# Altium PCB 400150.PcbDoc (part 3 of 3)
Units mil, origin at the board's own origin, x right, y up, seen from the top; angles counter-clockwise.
Board outline 4000 x 2500 mil, 4 copper layers (Top Layer, Mid-Layer 1, Mid-Layer 2, Bottom Layer), stack 62.293 mil thick; 200 components, 153 nets, 913 pads, 613 vias.
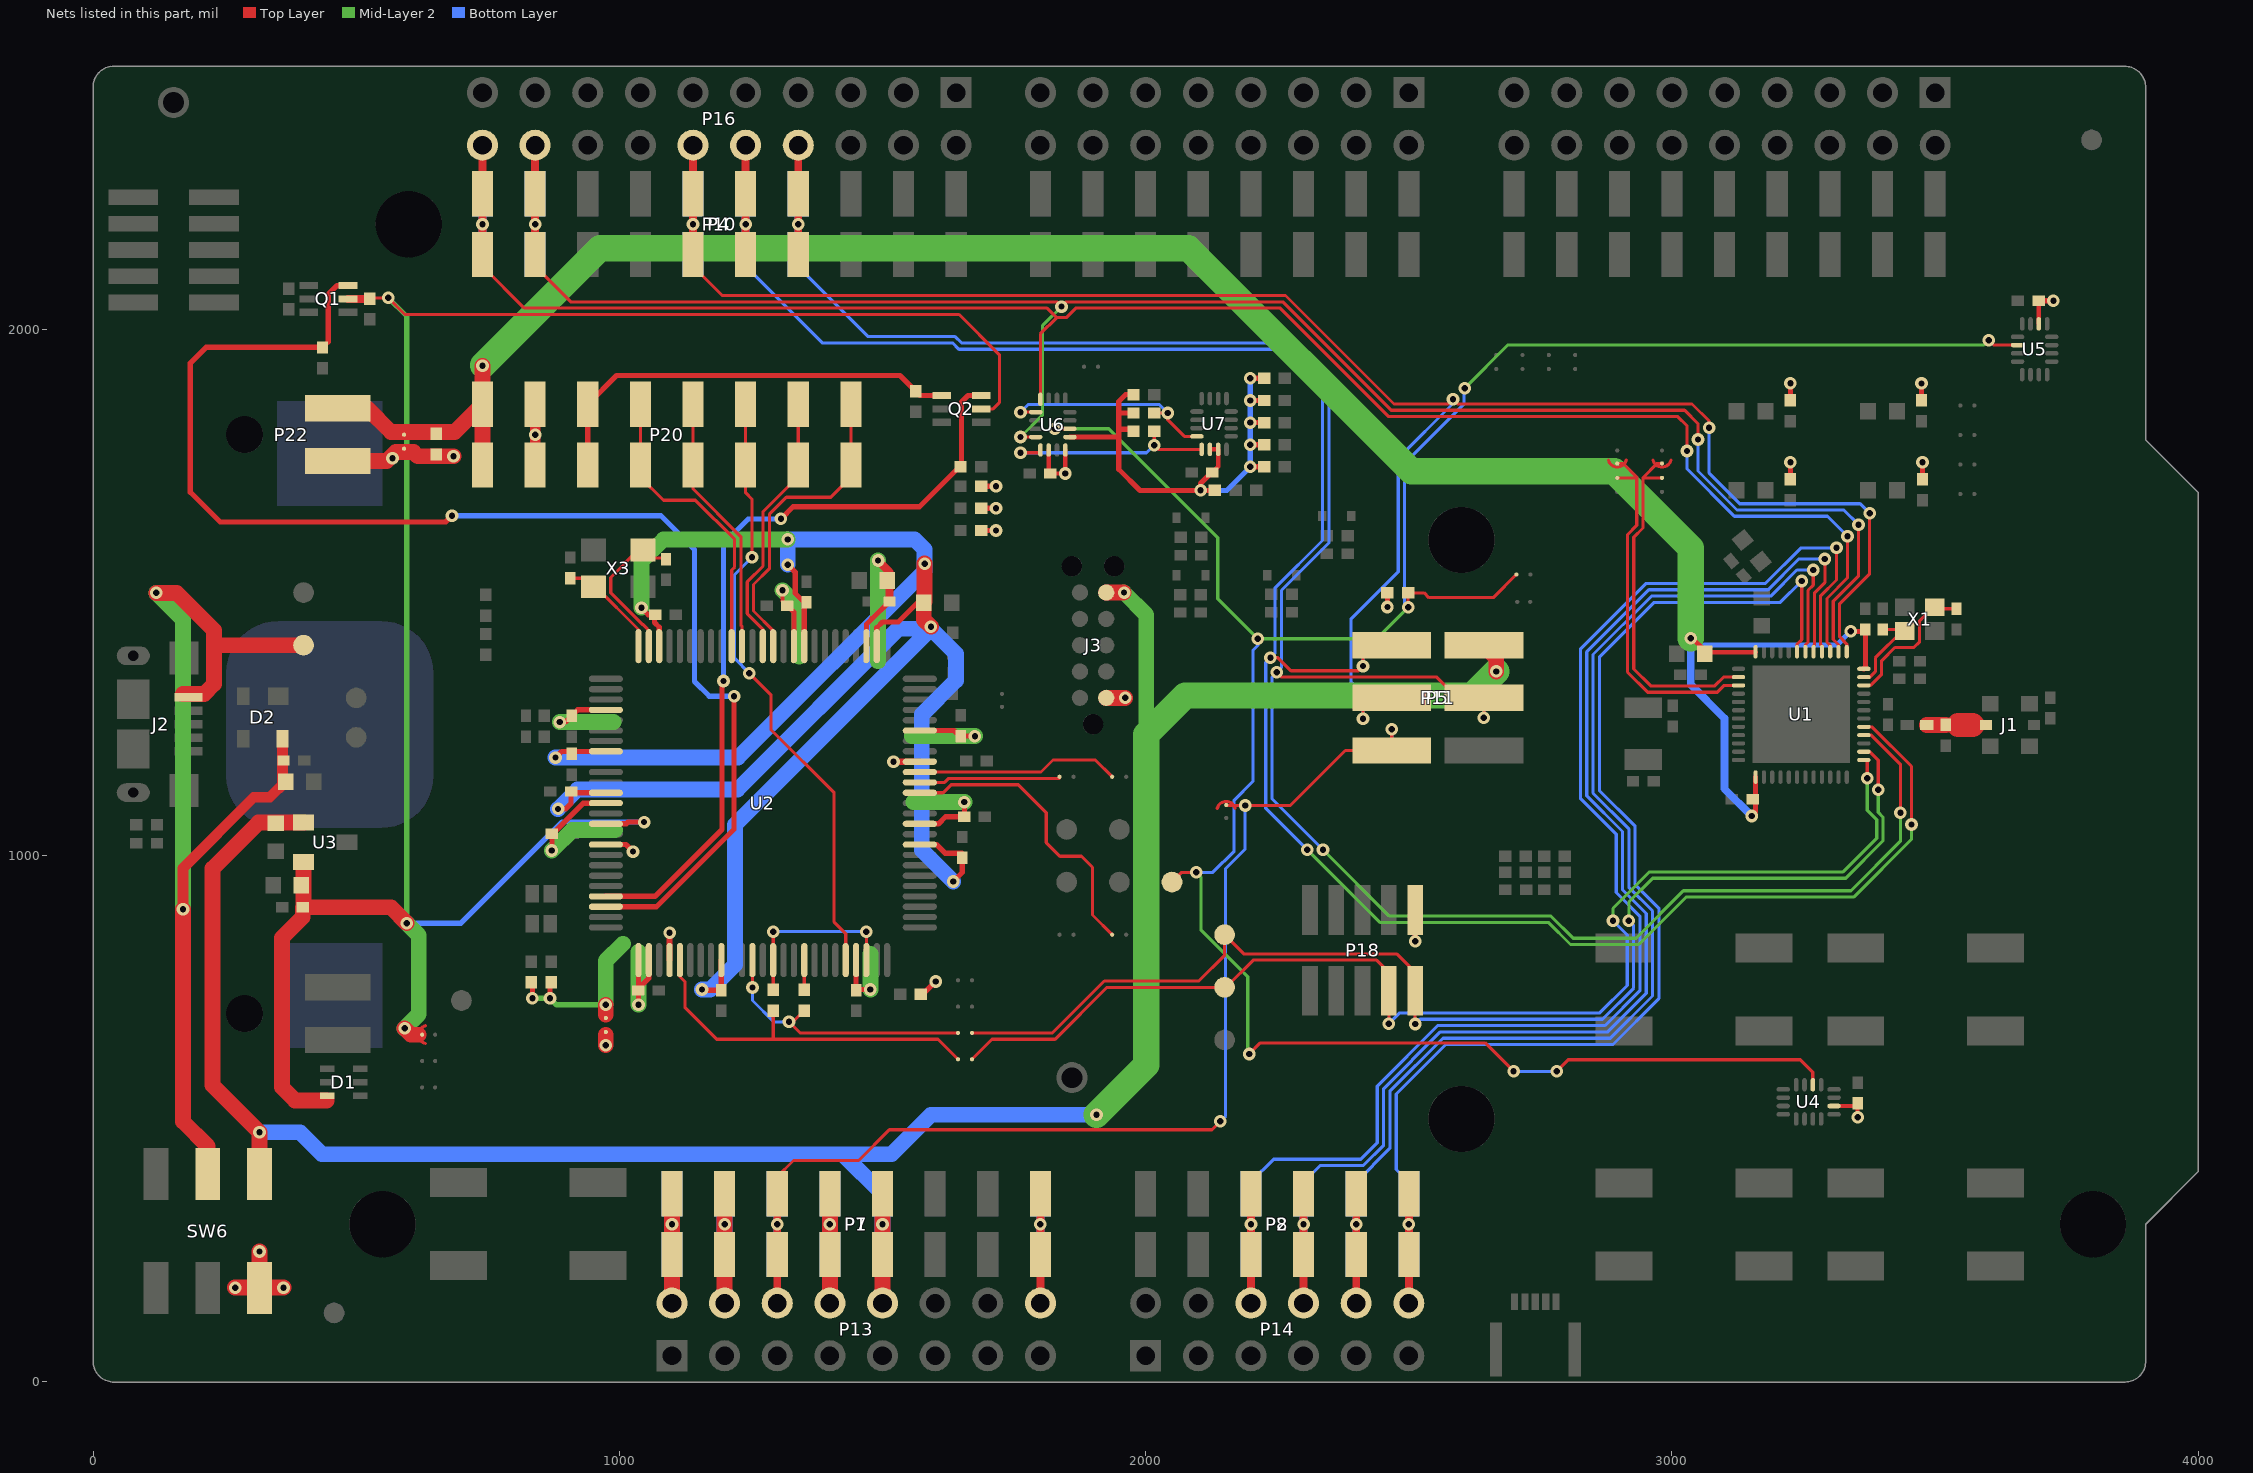
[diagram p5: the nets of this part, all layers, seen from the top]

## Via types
v1: diameter 24, hole 12, Top Layer to Bottom Layer, tented both sides, 576 vias
v2: diameter 24, hole 12, Top Layer to Bottom Layer, 21 vias
v3: diameter 25.98, hole 12.99, Top Layer to Bottom Layer, tented both sides, 16 vias

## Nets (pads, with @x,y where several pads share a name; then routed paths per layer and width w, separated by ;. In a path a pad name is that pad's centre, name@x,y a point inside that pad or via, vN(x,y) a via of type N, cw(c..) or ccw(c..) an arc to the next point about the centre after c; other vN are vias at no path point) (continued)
P0.23: P4.4 P5.4 P10.4 P11.4 P16.8 U1.28 | length 4457.1
  Top Layer w6: v1(2249,1348) 2258,1339 2553,1339 2592.4,1299.6 P5.4@2642.5,1299.6 v1(2642.5,1261.6) ; U1.28@3364.56,1228.79 3378.54,1228.79 3434,1173.33 v1(3434,1081.03)
  Top Layer w15: P4.4@1340,2118.6 v1(1340,2199.6) P4.4@1340,2257.28 P16.8@1340,2349.6
  Mid-Layer 2 w6: v1(2337,1011) 2463,885 2770.03,885 2812.03,843 2931.71,843 3021.71,933 3340.03,933 3434,1026.97 v1(3434,1081.03)
  Bottom Layer w6: P10.4@1340,2141.92 1340,2118.6 1472.6,1986 1638,1986 1650,1974 2287.65,1974 2348,1913.65 2348,1799 ; v1(2337,1011) 2240,1108 2240,1339 v1(2249,1348) 2258,1357 2258,1503.71 2348,1593.71 2348,1811.14 ; v1(2642.5,1261.6) 2642.5,1299.6 P11.4@2666.22,1299.6
  Bottom Layer w15: P10.4@1340,2141.92 v1(1340,2199.6) P10.4@1340,2257.28
P0.24: P4.5 P5.1 P10.5 P11.1 P16.10 U1.29 | length 4378.7
  Top Layer w6: v1(2237,1376) 2250.82,1376 2275.82,1351 2404,1351 v1(2413,1360) P5.1@2413,1399 ; U1.29@3364.56,1244.54 3379.76,1244.54 3455,1169.3 v1(3455,1059.03)
  Top Layer w15: P4.5@1240,2119.6 v1(1240,2199.6) P4.5@1240,2257.28 P16.10@1240,2349.6
  Mid-Layer 2 w6: v1(2307,1011) 2445,873 2765.06,873 2807.06,831 2936.68,831 3026.68,921 3345,921 3455,1031 v1(3455,1059.03)
  Bottom Layer w6: P10.5@1240,2141.92 1240,2119.6 1385.6,1974 1633.03,1974 1645.03,1962 2282.68,1962 2336,1908.68 2336,1799 ; v1@2237,1375 v1(2237,1376) ; v1(2307,1011) 2228,1090 2228,1367 v1(2237,1376) ; 2336,1816.11 2336,1598.68 2246,1508.68 2246,1385 v1(2237,1376) ; v1(2413,1360) P11.1@2413,1400
  Bottom Layer w15: P10.5@1240,2141.92 v1(1240,2199.6) P10.5@1240,2257.28
P0.25: P4.6 P5.3 P10.6 P11.3 P16.12 U1.37 | length 3916.4
  Top Layer w6: P4.6@1140,2119.6 1195.6,2064 2265.71,2064 2471.71,1858 2575,1858 v1(2584,1867) 2593,1858 3038,1858 3070.46,1825.54 v1(3070.46,1812.54) ; v1(2413,1260) P5.3@2413,1298 ; U1.37@3332.08,1387.25 3332.08,1401.77 3318.46,1415.38 3318.46,1478.52 3375.46,1535.52 v1(3375.46,1650.54)
  Top Layer w15: P4.6@1140,2119.6 v1(1140,2199.6) P4.6@1140,2257.28 P16.12@1140,2349.6
  Bottom Layer w6: v1(2413,1260) P11.3@2413,1298 ; P11.3@2420.19,1299.6 P11.3@2443.78,1299.6 2420.4,1299.6 2390,1330 2390,1449 2480,1539 2480,1754.87 2584,1858.87 v1(2584,1867) ; v1(3070.46,1812.54) 3070.46,1726.51 3128.44,1668.54 3357.46,1668.54 v1(3375.46,1650.54)
  Bottom Layer w15: P10.6@1140,2141.92 v1(1140,2199.6) P10.6@1140,2257.28
P0.26: P4.9 P10.9 P16.18 U1.38 U6.12 | length 3697.8
  Top Layer w6: P4.9@840,2119.6 907.6,2052 1831,2052 v1(1840,2043) 1849,2052 2260.68,2052 2466.68,1846 3024,1846 3049.46,1820.54 v1(3049.46,1790.54) ; v1(1762.14,1795.15) U6.12@1791.14,1795.15 ; U1.38@3316.33,1387.25 3316.33,1400.55 3306.46,1410.41 3306.46,1483.49 3354.46,1531.49 v1(3354.46,1628.54)
  Top Layer w15: P4.9@840,2119.6 v1(840,2199.6) P4.9@840,2257.28 P16.18@840,2349.6
  Mid-Layer 2 w6: v1(1762.14,1795.15) 1804.31,1837.31 1804.31,2007.31 v1(1840,2043)
  Bottom Layer w6: v1(3049.46,1790.54) 3049.46,1730.54 3123.46,1656.54 3326.46,1656.54 v1(3354.46,1628.54)
  Bottom Layer w15: P10.9@840,2141.92 v1(840,2199.6) P10.9@840,2257.28
P0.27: P4.10 P10.10 P16.20 U1.39 U6.8 | length 3620
  Top Layer w6: P4.10@740,2119.6 819.6,2040 1812.82,2040 1830.82,2022 ; U6.8@1800,1867 1800,1991.18 1830.82,2022 ; v1(3028.46,1768.54) 3028.46,1816.54 3011,1834 2461.71,1834 2255.71,2040 1867,2040 1849,2022 1830.82,2022 ; U1.39@3300.58,1387.25 3300.58,1399.32 3294.46,1405.44 3294.46,1488.46 3333.46,1527.46 v1(3333.46,1606.54)
  Top Layer w15: P4.10@740,2119.6 v1(740,2199.6) P4.10@740,2257.28 P16.20@740,2349.6
  Bottom Layer w6: v1(3028.46,1768.54) 3028.46,1734.56 3118.49,1644.54 3295.46,1644.54 v1(3333.46,1606.54)
  Bottom Layer w15: P10.10@740,2141.92 v1(740,2199.6) P10.10@740,2257.28
P0.28: P2.3 P8.3 P14.6 U1.40 | length 2770.9
  Top Layer w6: U1.40@3284.83,1387.25 3284.83,1398.1 3282.46,1400.47 3282.46,1493.54 3312.46,1523.54 v1(3312.46,1584.54)
  Top Layer w15: P14.6@2200,149.6 P2.3@2200,241.92 v1(2200,299.6) P2.3@2200,357.28
  Bottom Layer w6: P8.3@2200,357.28 2200,380 2243,423 2408.68,423 2440,454.32 2440,562 2555,677 2872.94,677 2939,743.06 2939,884.82 2894,929.82 2894,1040.76 2826,1108.76 2826,1392 2951,1517 3177.74,1517 3245.27,1584.54 v1(3312.46,1584.54)
  Bottom Layer w15: P8.3@2200,241.92 v1(2200,299.6) P8.3@2200,357.28
P0.29: P2.4 P8.4 P14.8 U1.41 | length 2614.3
  Top Layer w6: U1.41@3269.09,1387.25 3269.09,1398.87 3270.46,1400.25 3270.46,1498.54 3290.46,1518.54 v1(3290.46,1563.54)
  Top Layer w15: P14.8@2300,149.6 P2.4@2300,241.92 v1(2300,299.6) P2.4@2300,357.28
  Bottom Layer w6: P8.4@2300,379.6 2331.4,411 2413.68,411 2452,449.32 2452,557 2560,665 2877.91,665 2951,738.09 2951,889.79 2906,934.79 2906,1045.74 2838,1113.74 2838,1386.94 2956.06,1505 3182.71,1505 3241.24,1563.54 v1(3290.46,1563.54)
  Bottom Layer w15: P8.4@2300,241.92 v1(2300,299.6) P8.4@2300,379.6
P0.30: P2.5 P8.5 P14.10 U1.42 | length 2451.5
  Top Layer w6: U1.42@3253.34,1387.25 3253.34,1400.09 3258.46,1405.22 3258.46,1503.79 3268.46,1513.79 v1@3268.46,1533.54
  Top Layer w15: P14.10@2400,149.6 P2.5@2400,241.92 v1(2400,299.6) P2.5@2400,357.28
  Bottom Layer w6: P8.5@2400,379.6 2464,443.6 2464,552.03 2564.97,653 2882.88,653 2963,733.12 2963,894.76 2918,939.76 2918,1050.71 2850,1118.71 2850,1381.97 2961.03,1493 3187.68,1493 3237.21,1542.54 v1(3268.46,1542.54)
  Bottom Layer w15: P8.5@2400,241.92 v1(2400,299.6) P8.5@2400,379.6
P0.31: P2.6 P8.6 P14.12 U1.43 | length 2374.7
  Top Layer w6: U1.43@3237.59,1387.25 3237.59,1401.32 3246.46,1410.19 v1(3246.46,1521.54)
  Top Layer w15: P14.12@2500,149.6 P2.6@2500,241.92 v1(2500,299.6) P2.6@2500,357.28
  Bottom Layer w6: P8.6@2500,357.28 2500,379.6 2476,403.6 2476,547.06 2569.94,641 2887.85,641 2975,728.15 2975,899.73 2930,944.73 2930,1055.68 2862,1123.68 2862,1377 2966,1481 3205.93,1481 v1(3246.46,1521.54)
  Bottom Layer w15: P8.6@2500,241.92 v1(2500,299.6) P8.6@2500,357.28
PB5: Q2.3 R10.2 U2.97 | length 1490
  Top Layer w10: U2.97@974.38,922.43 1067.83,922.43 1195,1049.6 1195,1328.6 v1(1198,1331.6) ; v1(1307,1639.6) 1330,1662.6 1570.28,1662.6 R10.2@1645.75,1738.07 ; R10.2@1650,1739.77 1650,1861.6 1662.59,1874.19 Q2.3@1687.4,1874.19
  Bottom Layer w10: v1(1198,1331.6) 1198,1592.6 1245,1639.6 v1(1307,1639.6)
PB6: Q1.3 R11.2 U2.98 | length 2568
  Top Layer w10: R11.2@436,1965.29 R11.2@436.31,1965.6 ; Q1.3@484.4,2083.19 463.59,2083.19 447,2066.6 447,1976.29 R11.2@436.31,1965.6 ; v1(682,1645.6) 670,1633.6 241.68,1633.6 185,1690.28 185,1935.6 215,1965.6 R11.2@436.31,1965.6 ; U2.98@974.38,902.75 1070.78,902.75 1218,1049.97 v1(1218,1302.6) ; v1@1221,1302.6 v1@1221,1304.6
  Bottom Layer w10: v1(682,1645.6) 1079,1645.6 1143,1581.6 1143,1330.6 1171,1302.6 v1@1217,1302.6
RESET: P1.3 P5.5 P7.3 P11.5 P13.6 SB17.1 | length 2297.9
  Top Layer w6: P1.3@1300,357.28 1300,389.6 1331,420.6 1454.6,420.6 1513,479 2126,479 v1(2142,495) ; SB17.1@2154,1095 2167.61,1095 v1(2189,1095) 2274.9,1095 2379.5,1199.6 P5.5@2467.5,1199.6 ; P5.5@2467.69,1199.79 v1(2467.69,1240)
  Top Layer w15: P13.6@1300,149.6 P1.3@1300,241.92 v1(1300,299.6) P1.3@1300,357.28
  Bottom Layer w6: v1(2142,495) 2152,505 2152,975.32 2189,1012.32 v1(2189,1095) ; P11.5@2467.69,1199.6 v1(2467.69,1240)
  Bottom Layer w15: P7.3@1300,241.92 v1(1300,299.6) P7.3@1300,357.28
RF: C13.1 J1.1 L1.2 | length 62.9
  Top Layer w20: C13.1@3519.87,1248.16 C13.1@3520,1248.29
  Top Layer w30: L1.2@3484.17,1248.16 C13.1@3519.87,1248.16
  Top Layer w45: 3543.87,1248.16 3570.87,1248.16
RTS: SB24.2 U2.39 | length 576.5
  Top Layer w6: U2.39@1570.83,1119.28 1615.26,1119.28 1630.63,1134.65 1758,1134.65 1811.05,1081.59 1811.05,1024.55 1837,998.6 1878,998.6 1899,977.6 1899,887.01 SB24.2@1936.4,849.6
RXD: SB23.2 U2.40 | length 268.7
  Top Layer w6: U2.40@1570.83,1138.97 1617.98,1138.97 1625.66,1146.65 SB23.2@1836.4,1146.65
SCL_EXT: R30.1 U6.9 U7.12 | length 428.2
  Top Layer w6: v1(1762.14,1842.39) U6.9@1791.14,1842.39 ; R30.1@2016.31,1840.77 v1(2041.94,1840.77) 2041.94,1828 2073.56,1796.38 U7.12@2097.45,1796.38
  Bottom Layer w6: v1(1762.14,1842.39) 1776.52,1856.77 2025.39,1856.77 ; 2025.71,1857 v1(2041.94,1840.77)
SDA_EXT: R29.1 U6.13 U7.13 | length 417.5
  Top Layer w6: v1(1762.14,1765.15) U6.13@1800.14,1765.15 ; R29.1@2016.31,1805.77 v1(2016.31,1779.77) 2024.31,1771.77 U7.13@2106.31,1771.77
  Bottom Layer w6: v1(1762.14,1765.15) 2001.68,1765.15 v1(2016.31,1779.77)
SH_GND_DETECT: P20.8 U2.62 | length 601.1
  Top Layer w6: U2.62@1292.29,1397.83 1292.29,1427.31 1255,1464.6 1255,1514.92 1285,1544.92 1285,1648.2 1317.4,1680.6 1402,1680.6 1440,1718.6 P20.8@1440,1857.28
SH_RESET: P20.7 U2.63 | length 511.9
  Top Layer w6: U2.63@1272.61,1397.83 1272.61,1430.02 1243,1459.63 1243,1519.89 1273,1549.89 1273,1653.2 1340,1720.2 P20.7@1340,1741.92 P20.7@1340,1857.28
SH_SWDCLK: P20.5 U2.65 | length 498.1
  Top Layer w6: P20.5@1140,1857.28 1140,1696.6 1231,1605.6 1231,1437.69 1233.24,1435.45 U2.65@1233.24,1397.83
SH_SWDIO: P20.4 U2.66 | length 567.7
  Top Layer w6: P20.4@1040,1741.92 1040,1718.88 1083.84,1675.04 1144.56,1675.04 1219,1600.6 1219,1548.04 1213.55,1542.59 U2.66@1213.55,1397.83 ; P20.4@1040,1745.6 P20.4@1040,1857.28
SH_SWO: P20.6 U2.21 | length 1162
  Top Layer w6: P20.6@1240,1857.28 P20.6@1240,1741.92 1240,1689.04 1252,1677.04 v1(1252,1566.92) ; v1(1247,1346.6) 1288,1305.6 1288,1239.57 1408,1119.57 1408,873.6 1430.09,851.51 U2.21@1430.09,801.37
  Bottom Layer w6: v1(1247,1346.6) 1219,1374.6 1219,1533.92 v1(1252,1566.92)
SH_VTG: P20.3 Q2.4 R9.1 | length 941.6
  Top Layer w6: P20.3@940,1741.92 P20.3@940,1857.28
  Top Layer w10: P20.3@940,1741.92 P20.3@940,1857.28 994.72,1912 1533.28,1912 R9.1@1563,1882.29 1571.09,1874.19 Q2.4@1612.6,1874.19
SHIELD_DETECT: R39.1 SB19.2 TP15.1 U4.2 U5.2 U6.2 | length 4866.8
  Top Layer w6: v1(1827.52,1810.9) U6.2@1856.1,1810.9 ; TP15.1@2050,949.6 2068.4,968 v1(2096,968) ; v1(2197,623) 2218,644 2644.99,644 v1(2699,590) ; v1(2499,1472) 2498.69,1472.31 R39.1@2498.69,1499 2529,1499 2538,1490 2660.4,1490 SB19.2@2704.4,1534 ; v1(2781,590) 2803,612 3243.66,612 3267.54,588.12 U4.2@3267.54,564.48 ; v1(3602,1979) 3611,1970 3656.39,1970 U5.2@3656.52,1969.87
  Mid-Layer 2 w6: v1(1827.52,1810.9) 1930.1,1810.9 2137,1604 2137,1488 v1(2213,1412) 2439,1412 v1(2499,1472) ; v1(2096,968) 2105,959 2105,859 2194,770 2194,626 v1(2197,623) ; v1(2606,1888) 2688,1970 3593,1970 v1(3602,1979)
  Bottom Layer w6: v1(2096,968) 2127.71,968 2168,1008.29 2168,1105 2204,1141 2204,1390 2213,1399 v1(2213,1412) ; v1(2499,1472) 2492,1479 2492,1745.3 2605,1858.3 2605,1887 v1(2606,1888) ; v1(2699,590) v1(2781,590)
SWDCLK: P18.4 SB21.1 TP10.1 U1.25 | length 2327.9
  Top Layer w6: SB21.1@1670.02,613 1708.02,651 1827.97,651 1926.57,749.6 TP10.1@2150,749.6 2152.6,749.6 2204.23,801.23 2438.77,801.23 2462,778 P18.4@2462,746.23 ; v1(2462,680.23) P18.4@2462,743 ; v1(3371,1147.03) U1.25@3371,1182.03
  Mid-Layer 2 w6: v1(2888,876) 2888,899.69 2957.31,969 3325.03,969 3389,1032.97 3389,1068 3371,1086 v1(3371,1147.03)
  Bottom Layer w6: v1(2462,680.23) 2482.77,701 2863,701 2915,753 2915,849 v1(2888,876)
SWDIO: P18.2 SB20.1 TP9.1 U1.26 | length 2399
  Top Layer w6: SB20.1@1670.02,663 1823,663 1921.6,761.6 2101,761.6 2150,810.6 TP9.1@2150,849.6 ; TP9.1@2150.3,849.3 2186.37,813.23 2476.77,813.23 2512,778 P18.2@2512,746.23 ; v1(2512,680) P18.2@2512,743 ; U1.26@3364.56,1197.29 3375.97,1197.29 3392,1181.26 v1(3392,1125.03)
  Mid-Layer 2 w6: v1(2918,876) 2918,911.69 2963.31,957 3330.03,957 3401,1027.97 3401,1072.97 3392,1081.97 v1(3392,1125.03)
  Bottom Layer w6: v1(2512,680) 2521,689 2867.97,689 2927,748.03 2927,867 v1(2918,876)
TCKIN: R16.2 SB21.2 U2.5 | length 707.7
  Top Layer w6: U2.5@1115.13,801.37 1115.13,770.08 1124.61,760.6 1124.61,711.6 1185.21,651 1292.35,651 ; R16.2@1292.35,705.31 1292.35,651 ; SB21.2@1643.42,613 1605.42,651 1292.35,651
TCKOUT: R16.1 U2.14 U2.23 | length 329.6
  Top Layer w6: 1292.29,756.97 U2.14@1292.29,801.37 v1(1292.29,855.37) ; v1(1469.29,855.37) 1469.29,801.84 1469.61,801.52 U2.23@1469.46,801.37
  Bottom Layer w6: v1(1292.29,855.37) v1(1469.29,855.37)
TMSIN: R15.2 SB20.2 U2.12 | length 530.6
  Top Layer w6: v1(1252.92,749.37) U2.12@1252.92,801.37 ; R15.2@1351.35,705.31 1330.03,684 v1(1322.35,684) 1343.35,663 SB20.2@1643.42,663
  Bottom Layer w6: v1(1252.92,749.37) 1252.92,724.54 1293.46,684 v1(1322.35,684)
TMSOUT: R15.1 U2.17 | length 56.7
  Top Layer w6: R15.1@1351.35,744.69 U2.17@1351.35,801.37
TXD: SB25.2 U2.41 | length 388.3
  Top Layer w6: U2.41@1570.83,1158.65 1801.05,1158.65 1824,1181.6 1904.4,1181.6 SB25.2@1936.4,1149.6
USB_DETECT: C17.2 C18.2 D1.6 Q1.2 Q2.2 R7.1 SB10.2 U2.90 U3.2 | length 4223
  Top Layer w6: R7.1@526,2058.29 527.32,2059.6 v1(561,2059.6) 592.6,2028 1645.6,2028 1722.17,1951.43 1722.17,1860.64 1710.13,1848.6 Q2.2@1687.4,1848.6
  Top Layer w10: U2.90@974.38,1060.23 1013.1,1060.23 1016.47,1063.6 v1(1047,1063.6)
  Top Layer w15: Q1.2@484.4,2057.6 R7.1@525.32,2057.6
  Top Layer w30: U3.2@400,987.8 400,902.92 C18.2@398.68,901.6 ; 444,534.6 384,534.6 359,559.6 359,843.6 398.68,883.28 C18.2@398.68,901.6 ; v1(592,671.6) 604,659.6 619,659.6 ; v1(596,871.6) 566,901.6 C18.2@398.68,901.6
  Mid-Layer 2 w10: v1(561,2059.6) 596,2024.6 v1(596,871.6)
  Mid-Layer 2 w30: v1(592,671.6) 619,698.6 619,848.6 v1(596,871.6)
  Bottom Layer w10: v1(596,871.6) 699,871.6 891,1063.6 v1(1047,1063.6)
V5V: C16.2 J3.5 P1.5 P5.2 P7.5 P11.2 P13.10 SW6.6 U3.1 | length 4892.3
  Top Layer w30: SW6.6@316.43,394.87 v1(316.43,474.17) 227,563.6 227,975.17 314.43,1062.6 U3.1@400,1062.6 ; P13.10@1500,149.6 P1.5@1500,241.92 v1(1500,299.6) P1.5@1500,357.28 ; J3.5@1925,1499.6 v1@1958,1499.6 ; P5.2@2642.5,1399.6 2666.22,1375.88 v1(2666.22,1349.82)
  Mid-Layer 2 w30: v1(1959,1499.6) 2001,1457.6 2001,1138
  Mid-Layer 2 w50: v1(1906.6,507.6) 2001,602 2001,1230 2075,1304 2620.4,1304 v1(2666.22,1349.82)
  Bottom Layer w30: v1(316.43,474.17) 393.43,474.17 435,432.6 1424.68,432.6 ; P7.5@1500,241.92 v1(1500,299.6) P7.5@1500,357.28 1424.68,432.6 ; v1(1906.6,507.6) 1592,507.6 1517,432.6 1424.68,432.6 ; v1(2666.22,1349.82) P11.2@2666.22,1399.6
VBUS: C20.2 C21.2 D2.4 J2.1 SW6.5 TP3.1 | length 2047.6
  Top Layer w20: v1(171,898) 171,976 305.6,1110.6 336.03,1110.6 C20.2@366.03,1140.6 ; C20.2@360.01,1137.61 D2.4@360.01,1222.25
  Top Layer w30: v1(120,1499) 159,1499 230,1428 230,1325.76 211.24,1307 J2.1@171,1307 ; v1(171,898) 171,494.6 218,447.6 SW6.5@218,394.87 ; 231.4,1399.6 TP3.1@400,1399.6
  Mid-Layer 2 w30: v1(120,1499) 171,1448 v1(171,898)
VCORE: C25.2 C27.2 C31.2 C34.2 C36.1 C39.2 C40.2 U2.9 U2.34 U2.52 U2.59 U2.73 U2.83 U2.87 | length 4851.6
  Top Layer w10: v1(878.61,1186.13) 890.08,1197.6 U2.83@973.95,1197.6 ; v1(883.61,1088.6) 897.71,1088.6 908.29,1099.18 C40.2@908.29,1121.6 ; C40.2@914.96,1119.28 U2.87@974.38,1119.28 ; v1(1042,1470.6) 1055,1457.6 C36.1@1066.96,1457.6 ; C36.1@1067.92,1457.6 C36.1@1066.96,1457.6 ; U2.73@1075.76,1397.83 1075.76,1433.84 1066.96,1442.64 C36.1@1066.96,1457.6 ; v1(1157,745.6) 1158.31,744.28 C25.2@1193.61,744.28 ; C25.2@1193.87,745.27 U2.9@1193.87,801.37 ; v1(1320,1552.6) 1331,1541.6 1334,1538.6 1334,1498.24 1340,1492.24 C34.2@1353.46,1478.77 ; U2.59@1351.35,1397.83 1351.35,1476.65 C34.2@1353.46,1478.77 ; C34.2@1355.61,1480.91 C34.2@1353.46,1478.77 ; U2.52@1489.14,1397.83 1489.14,1432.71 1500.03,1443.6 1530,1443.6 1567,1480.6 C31.2@1578.42,1480.6 ; U2.34@1570.83,1020.86 1602.35,1020.86 1618.61,1004.6 C27.2@1649.94,1004.6 ; v1(1634.61,950.6) 1651.61,967.6 C27.2@1651.61,995.91 ; C27.2@1650.92,998.28 C27.2@1650.92,1004.6
  Top Layer w30: v1(1580,1554.6) 1580,1482.18 C31.2@1578.42,1480.6 1578.42,1448.18 v1(1592,1434.6)
  Mid-Layer 2 w30: v1(1042,1470.6) 1042,1558.6 1084,1600.6 v1(1320,1600.6)
  Bottom Layer w30: v1(878.61,1186.13) 1225.53,1186.13 1580,1540.6 v1(1580,1554.6) 1580,1581.6 1561,1600.6 v1(1320,1600.6) v1(1320,1552.6) ; v1(883.61,1088.6) 920.61,1125.6 1224.61,1125.6 1530,1430.99 v1@1592,1430.99 ; v1(1157,745.6) 1172.61,745.6 1219.61,792.6 1219.61,1058.6 v1@1592,1430.99 ; v1(1634.61,950.6) 1574.61,1010.6 1574.61,1267.76 1639.61,1332.76 1639.61,1383.39 v1@1592,1430.99
VDD: C44.2 C45.2 C46.2 J3.1 P1.1 P1.2 P1.4 P7.1 P7.2 P7.4 P13.2 P13.4 P13.8 P18.1 P20.2 P22.2 R1.2 R2.2 R3.2 R4.2 R5.2 R6.1 R21.2 R22.2 R23.2 R39.2 SB9.2 SB29.2 SW6.3 U4.14 U5.14 U6.14 U6.16 | length 2206.4
  Top Layer w6: P20.2@840,1728.6 P20.2@840,1741.92
  Top Layer w8: C46.2@1812.75,1730.34 1817.15,1725.94 C46.2@1817.31,1725.78 ; C46.2@1815.75,1729.02 U6.14@1815.75,1770.54 ; C46.2@1818.99,1725.77 v1(1846.99,1725.77) ; v1@1847.24,1725.77 U6.16@1847.24,1770.54 ; U4.14@3307.89,524.13 3352.47,524.13 C44.2@3352.66,524.31 ; v1(3352.66,503) C44.2@3352.66,524.31 ; C44.2@3352.66,529.32 C44.2@3352.66,524.31 ; C45.2@3696.69,2054 3696.87,2053.81 U5.14@3696.87,2010.23
  Top Layer w10: R5.2@1572.69,736.6 1577,736.6 v1(1601,760.6) ; R21.2@1687.53,1617.6 v1(1715.69,1617.6) ; R22.2@1687.53,1659.6 v1(1715.69,1659.6) ; R23.2@1687.53,1701.6 v1(1715.69,1701.6) ; v1(2459.31,1472.31) R39.2@2459.31,1499 ; v1(2512,837) P18.1@2512,896.54 ; R3.2@3225.01,1714.68 v1(3225.01,1746.99) ; R1.2@3225.01,1864.68 v1(3225.01,1897.31) ; R2.2@3474.01,1864.68 v1(3474.01,1896.99) ; R4.2@3476.01,1714.68 v1(3476.01,1746.99) ; C45.2@3696.69,2054 v1(3724.69,2054)
  Top Layer w15: v1(1400,299.6) P1.4@1400,357.28
  Top Layer w20: P20.2@840,1741.92 P20.2@840,1857.28
  Top Layer w30: v1(270,179.06) v1(362,179.06) ; SW6.3@316.42,176.35 v1(316.42,247.62) ; P22.2@465,1749.6 558,1749.6 575,1766.6 609,1766.6 617,1758.6 v1(685,1758.6) ; v1(974.38,639.78) 974.38,658.78 ; P13.2@1100,149.6 P1.1@1100,241.92 P1.1@1100,357.28 ; P13.4@1200,149.6 v1(1200,299.6) P1.2@1200,357.28 ; P13.8@1400,149.6 P1.4@1400,357.28 ; J3.1@1925,1299.6 v1(1961,1299.6)
  Bottom Layer w30: P7.1@1100,241.92 P7.1@1100,357.28 ; P7.2@1200,241.92 P7.2@1200,357.28 ; P7.4@1400,241.92 P7.4@1400,357.28
  other v1: 1100,299.6 569,1754.6 840,1799.6
VDD_NRF: C5.1 C8.1 C9.1 P20.1 P22.1 R6.2 SB9.1 U1.13 U1.36 U1.48 | length 4322.1
  Top Layer w9: v1(3035.62,1412.92) 3038.89,1412.92 3062.2,1389.62 3065.54,1386.27 U1.48@3158.46,1386.27 ; v1(3151.46,1075.16) 3158.85,1082.55 U1.13@3158.85,1149.07
  Top Layer w10: v1(3339.46,1426.16) 3340.15,1425.47 3367.46,1425.47 3367.46,1357.68 U1.36@3364.56,1354.77
  Top Layer w15: C9.1@3062.2,1382.92 C9.1@3062.2,1389.62
  Top Layer w30: P22.1@465,1849.6 521,1849.6 566,1804.6 687.32,1804.6 P20.1@740,1857.28 ; P20.1@740,1741.92 P20.1@740,1857.28 ; v1(740,1930.6) P20.1@740,1857.28
  Mid-Layer 2 w50: v1@741,1931.6 963.4,2154 2081,2154 2505,1730 2890,1730 3035.62,1584.38 v1(3035.62,1412.92)
  Bottom Layer w10: v1(3035.62,1412.92) 3048.39,1400.16 3313.46,1400.16 ; 3313.87,1400.16 3313.46,1400.16 ; v1(3339.46,1426.16) 3313.46,1400.16
  Bottom Layer w15: v1(3035.62,1412.92) 3035.62,1324.82 3099.52,1260.92 3099.52,1127.11 v1(3151.46,1075.16)
VDD_SAM: C24.2 C26.2 C28.2 C29.2 C32.2 C33.2 C35.2 C38.2 C41.2 R19.2 R20.2 SB29.1 U2.1 U2.2 U2.4 U2.22 U2.36 U2.42 U2.45 U2.53 U2.60 U2.79 U2.88 U2.92 | length 2470.3
  Top Layer w6: U2.88@974.38,1099.6 U2.88@981,1099.6
  Top Layer w8: v1(1310,1503.92) 1310,1483.89 C35.2@1319.29,1474.6
  Top Layer w10: v1@834.87,729.6 R20.2@834.87,758.91 ; v1(868.34,728.91) R19.2@868.34,758.91 ; v1@871.92,1009.6 C41.2@871.92,1041.6 ; C41.2@874.92,1042.91 931.61,1099.6 U2.88@974.38,1099.6 ; v1(886.61,1253.6) 897.92,1253.6 C38.2@909.61,1265.28 ; C38.2@909.92,1265.6 921.09,1276.76 U2.79@974.38,1276.76 ; U2.92@974.38,1020.86 1012.63,1020.86 v1(1025.94,1007.54) ; U2.1@1036.39,801.37 1036.39,743.6 1036.44,743.55 v1(1036.44,716.37) ; C24.2@1036.61,747.6 1056.07,767.06 U2.2@1056.07,801.37 ; C35.2@1319.29,1474.6 1331.66,1462.23 U2.60@1331.66,1397.83 ; C26.2@1449.77,752.12 U2.22@1449.77,801.37 ; C26.2@1451.32,745.6 v1(1477,745.6) ; U2.53@1469.46,1397.83 1469.46,1439.45 1479.8,1449.8 1509.18,1479.17 C32.2@1509.18,1482.6 ; U2.36@1570.83,1060.23 1606.24,1060.23 1619.61,1073.6 C28.2@1654.92,1073.6 1655.61,1074.28 v1(1655.61,1101.6) ; U2.42@1570.83,1178.34 U2.42@1571.57,1177.6 ; U2.45@1570.83,1237.39 1635.81,1237.39 C29.2@1643.29,1229.91 ; C29.2@1648.61,1226.91 v1(1675.61,1226.91)
  Top Layer w12: U2.4@1095.44,801.37 v1(1095.44,853.37) ; v1(1520.83,1178.34) U2.42@1570.83,1178.34
  Top Layer w15: v1(1491.61,1560.6) 1513.29,1538.91 C32.2@1513.29,1482.6
  Top Layer w30: 974.38,697.38 v1(974.38,716.38)
  Mid-Layer 2 w10: v1(834.87,728.91) v1(868.34,728.91) 880.87,716.38 v1(974.38,716.38)
  Mid-Layer 2 w30: v1(871.61,1009.6) 910.35,1048.34 991.83,1048.34 ; v1(886.61,1253.6) 988.83,1253.6 ; v1(974.38,716.38) 974.38,799.88 1006.83,832.34 ; v1(1036.44,716.37) 1036.44,817.34 ; v1(1310,1503.92) 1341.83,1472.09 1341.83,1378.34 ; v1(1477,745.6) 1477,813.34 ; 1491.61,1369.34 v1(1491.61,1560.6) ; 1555.83,1226.91 v1(1675.61,1226.91) ; 1558.83,1101.6 v1(1655.61,1101.6)
VEXT: C47.2 R29.2 R30.2 R31.2 R32.2 R33.2 R34.2 R35.2 R36.2 R37.2 U6.1 U7.14 U7.15 | length 1033.9
  Top Layer w8: U7.14@2122.06,1771.77 U7.15@2137.81,1771.77 2137.81,1738.91 C47.2@2126.68,1727.77
  Top Layer w10: U6.1@1856.1,1795.15 1948.94,1795.15 ; R29.2@1976.94,1805.77 1972.94,1809.77 1952.01,1809.77 1948.94,1812.84 ; R30.2@1976.94,1840.77 1948.94,1840.77 ; R31.2@1976.94,1875.77 1962.17,1875.77 1948.94,1862.54 1948.94,1840.77 ; C47.2@2125.99,1728.46 2104.31,1706.77 v1(2104.31,1693.77) ; R37.2@2131.62,1693.77 v1(2104.31,1693.77) ; v1(2198.94,1738.62) R32.2@2225.25,1738.62 ; v1(2198.94,1780.62) R33.2@2225.25,1780.62 ; v1(2198.94,1822.62) R34.2@2225.25,1822.62 ; v1(2198.94,1864.62) R35.2@2225.25,1864.62 ; v1(2198.94,1906.62) R36.2@2225.25,1906.62 ; 1948.94,1795.15 1948.94,1812.84 ; 1948.94,1795.15 1948.94,1734 1989.16,1693.77 v1(2104.31,1693.77) ; 1948.94,1812.84 1948.94,1840.77
  Bottom Layer w10: v1(2104.31,1693.77) 2154.08,1693.77 v1(2198.94,1738.62) v1(2198.94,1780.62) v1(2198.94,1822.62) v1(2198.94,1864.62) v1(2198.94,1906.62)
VIN: P1.8 P7.8 P13.16 | length 323
  Top Layer w15: P13.16@1800,149.6 P1.8@1800,241.92 v1(1800,299.6) P1.8@1800,357.28
  Bottom Layer w15: P7.8@1800,241.92 v1(1800,299.6) P7.8@1800,357.28
XC1: C1.1 U1.34 X1.1 | length 274.7
  Top Layer w6: U1.34@3364.56,1323.28 3377.32,1323.28 3398.35,1344.32 3398.35,1370.13 3423.39,1395.16 3459.46,1395.16 3470.46,1406.16 3470.46,1446.16 3493.15,1468.85 C1.1@3540.46,1468.85
XC2: C2.1 U1.35 X1.3 | length 167.4
  Top Layer w6: U1.35@3364.56,1339.03 3375.97,1339.03 3386.35,1349.42 3386.35,1375.6 3437.27,1426.52 X1.3@3441.92,1426.52 ; C2.1@3400.46,1429.47 X1.3@3438.97,1429.47
XIN: C22.1 U2.75 X3.3 | length 201.7
  Top Layer w6: C22.1@906.61,1526.91 934.34,1526.91 X3.3@950.6,1510.66 ; X3.3@950.6,1510.54 955.28,1510.54 1036.39,1429.44 U2.75@1036.39,1397.83
XL1: SB2.2 SB4.1 U1.2 | length 673.2
  Top Layer w6: SB2.2@2981,1717.6 2945.4,1717.6 2945,1718 ; SB4.1@2981,1745 2972,1745 2945,1718 ; U1.2@3126.37,1339.03 3097.75,1339.03 3081.1,1322.37 2959.63,1322.37 2927.46,1354.54 2927.46,1604.68 2945,1622.22 2945,1718
XL2: SB1.2 SB3.1 U1.3 | length 693.2
  Top Layer w6: SB1.2@2896,1717.6 2931.6,1717.6 ; SB3.1@2896,1745 2907,1745 2933,1719 2933,1627.19 2915.46,1609.65 2915.46,1348.54 2953.63,1310.37 3086.07,1310.37 3098.98,1323.28 U1.3@3126.37,1323.28
XOUT: C23.1 U2.74 X3.1 | length 294
  Top Layer w6: U2.74@1056.07,1397.83 1056.07,1427.53 1050,1433.6 1044.29,1439.31 1043.48,1439.31 983.61,1499.19 983.61,1528.21 1036.06,1580.66 X3.1@1044.61,1580.66 1059.99,1565.28 C23.1@1088.61,1565.28
pads on no net: Bat1.0 Fid1.0 Fid2.0 J2.4 J2.6@76.53,1119.68 J2.6@76.53,1379.52 J3.0 J3.7 J3.9 P18.7 P18.8 P19.7 P19.8 P21.0 P22.0 P23.0 P23.1 P23.3 P23.5 SW6.1 SW6.4 U1.44 U2.6 U2.8 U2.10 U2.11 U2.13 U2.15 U2.16 U2.19 U2.25 U2.26 U2.28 U2.29 U2.30 U2.31 U2.32 U2.33 U2.37 U2.44 U2.48 U2.49 U2.50 U2.58 U2.64 U2.69 U2.86 U2.93 U2.94 U2.95 U2.96 U2.99 U2.100 U4.10 U5.10 U6.3 U6.7 U6.10 U6.11 U6.15
copper on no net:
  other v1: 2067,709.6 1949,782.6

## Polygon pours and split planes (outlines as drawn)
VDD_SAM on Mid-Layer 2 "NONET_L03_P008" (solid, pour order 8): 962,1408.34 962,788.6 1580.83,788.6 1580.83,1408.34
VDD on Mid-Layer 2 "Mid_Layer_2-VDD" (solid, remove dead copper, pour order 10): -104.87,-142.03 -104.87,2619.48 -96.26,2635.53 4116.93,2635.53 4127.69,2655.6 4127.69,-134 4132,-142.03
GND on Bottom Layer "Bottom_Layer-GND" (solid, remove dead copper, pour order 6): -410.29,-103.54 -410.29,2687.09 -400.99,2703.32 4149.72,2703.32 4161.35,2723.6 4161.35,-95.43 4166,-103.54
GND on Top Layer "Top_Layer-GND" (solid, remove dead copper, pour order 12): -140.68,-93.7 -140.68,2627.01 -132.15,2642.83 4042.07,2642.83 4052.73,2662.6 4052.73,-85.79 4057,-93.7
GND on Mid-Layer 1 "Mid_Layer_1-GND" (solid, remove dead copper, pour order 7): -138.74,-96.93 -138.74,2579.59 -129.94,2595.15 4177.59,2595.15 4188.6,2614.6 4188.6,-89.15 4193,-96.93

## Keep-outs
Keep-Out Layer:
  circle w6: c2600,499.6 r94.49
  circle w6: c600,2199.6 r94.49
  circle w6: c2600,1599.6 r94.49
  circle w6: c3800,299.6 r94.49
  circle w6: c550,299.6 r94.49
  lines w10: 3861,-0.4 ccw(c3860.5,39.1) 3900,39.6 3900,299.6 4000,399.6 4000,1689.6 3900,1789.6 3900,2459.6 ccw(c3860,2459.6) 3860,2499.6 40,2499.6 ccw(c39.5,2460.1) 0,2460.6 0,39.6 ccw(c40,39.6) 40,-0.4 3862,-0.4
Mechanical 3:
  lines w1: 209,1333.56 293,1333.56 ; 217,1208.6 411.61,1208.6 428.78,1191.43 527.44,1191.43 ccw(c527.44,1234.88) 558.16,1204.16 703.61,1349.6 cw(c741.44,1311.77) 741.44,1365.27 764.61,1365.27 ; 390,1333.56 467.04,1333.56 ccw(c467.04,1356.56) 483.3,1340.3 634.85,1491.85 cw(c686.61,1440.1) 686.61,1513.29 ; 686.61,1513.6 927.61,1513.6 cw(c927.61,1465.32) 961.75,1499.46 1059.68,1401.53 ; 764.11,1365.27 cw(c764.11,1316.99) 798.25,1351.13 896.18,1253.2 ; 997.8,1252.14 ccw(c997.8,1339.64) 1059.67,1401.52

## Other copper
Top Layer:
  rectangle net ANT: 3937,537.6 3987,567.6
  pour cut-out: 2383,1217.6 2680.03,1217.6 2679.97,1287.6 2383,1287.6
  pour cut-out: 3739.97,-50.4 4010.28,-50.4 4008.77,1787.6 3740.14,1787.6
  pour cut-out: 372,1318.6 460,1318.6 460,1251.6 372,1251.6
  pour cut-out: 342,730.6 430,730.6 430,560.6 342,560.6
  pour cut-out: -9.02,1110 111.17,1110 110.94,1388.6 -8.99,1388.6
  pour cut-out: 3470.46,1205.16 3362.46,1205.16 3362.46,1319.16 3470.46,1319.16
  pour cut-out: 2264,1601 2326.5,1663.5 2326.5,1598 2306,1577.5 2306,1542.6 2264,1542.6
Mid-Layer 1:
  pour cut-out: 3742.87,1183.16 3386.87,1183.16 3386.87,1313.16 3742.87,1313.16
  pour cut-out: 3739.97,-50.4 4010.28,-50.4 4008.77,1787.6 3740.14,1787.6
Mid-Layer 2:
  pour cut-out: 990.83,792.34 990.83,702.34 1020.83,702.34 1020.83,792.34
  pour cut-out: 3742.87,1183.16 3386.87,1183.16 3386.87,1313.16 3742.87,1313.16
  pour cut-out: 3739.97,-50.4 4010.28,-50.4 4008.77,1787.6 3740.14,1787.6
Bottom Layer:
  pour cut-out: 3739.97,-50.4 4010.28,-50.4 4008.77,1787.6 3740.14,1787.6

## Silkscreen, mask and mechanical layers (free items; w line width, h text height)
Top Overlay:
  circle w15: c1930,374.6 r7.07
  circle w15: c1030,374.6 r7.07
  circle w15: c3569,2125 r7.07
  circle w15: c2570,2124.6 r7.07
  circle w15: c1710,2124.6 r7.07
  lines w6: 2898,1084.16 3578.46,1084.16 3578.46,1634.16 2898,1634.16 2898,1084.16
  lines w10: 420,2399.6 3730,2399.6 ; 560,2449.6 670,2449.6 ; 660,2449.6 640,2459.6 640,2439.6 670,2449.6 ; 780,99.6 2550,99.6 ; 920,49.6 1030,49.6 ; 1020,49.6 1000,59.6 1000,39.6 1030,49.6 ; 3577,2447.6 3597,2437.6 3597,2457.6 3567,2447.6 ; 3677,2447.6 3567,2447.6 ; 670,2449.6 640,2469.6 640,2429.6 670,2449.6 ; 1030,49.6 1000,69.6 1000,29.6 1030,49.6 ; 3567,2447.6 3597,2427.6 3597,2467.6 3567,2447.6
  text "GND" at 420,2429.6 h70
  text "GND" at 3707,2427.6 h70
  text "GND" at 97,2329.6 h70
  text "0071KJP" at 3851,2068 h60 r90
  text "400150" at 3799.69,2065.44 h80 r90
  text "P0.27" at 760,1963.6 h70 r90
  text "P0.26" at 860,1963.6 h70 r90
  text "P0.02" at 960,1963.6 h70 r90
  text "GND" at 1060,1963.6 h70 r90
  text "P0.25" at 1160,1963.6 h70 r90
  text "P0.24" at 1260,1963.6 h70 r90
  text "P0.23" at 1360,1963.6 h70 r90
  text "P0.22" at 1460,1963.6 h70 r90
  text "P0.20" at 1560,1963.6 h70 r90
  text "P0.19" at 1660,1963.6 h70 r90
  text "P0.18" at 1820,1963.6 h70 r90
  text "P0.17" at 1920,1963.6 h70 r90
  text "P0.16" at 2020,1963.6 h70 r90
  text "P0.15" at 2120,1963.6 h70 r90
  text "P0.14" at 2220,1963.6 h70 r90
  text "P0.13" at 2320,1963.6 h70 r90
  text "P0.12" at 2420,1963.6 h70 r90
  text "P0.10" at 2720,1963.6 h70 r90
  text "P0.09" at 2820,1963.6 h70 r90
  text "P0.08" at 2920,1963.6 h70 r90
  text "P0.07" at 3020,1963.6 h70 r90
  text "P0.06" at 3120,1963.6 h70 r90
  text "P0.05" at 3220,1963.6 h70 r90
  text "P0.21" at 3320,1963.6 h70 r90
  text "P0.01" at 3420,1963.6 h70 r90
  text "P0.00" at 3521,1963.6 h70 r90
  text "Debug out" at 16,1958.6 h80
  text "LED1" at 3065.01,1871.99 h80
  text "LED2" at 3309.01,1871.99 h80
  text "GPIO" at 2756,1735 h60
  text "LED3" at 3060.01,1722.99 h80
  text "LED4" at 3310.01,1722.99 h80
  text "XTAL" at 2756,1685 h60
  text "nRF current" at 143,1638.6 h80
  text "VTG" at 957,1615.98 h55 r90
  text "VDD / nRF" at 778,1613 h55 r90
  text "VDD" at 857,1613.46 h55 r90
  text "(ARDUINO D0) P0.11" at 2521,1608 h70 r90
  text "SWD / IO" at 1083,1604 h55 r90
  text "SWD / CLK" at 1183,1604 h55 r90
  text "SWO" at 1257,1603.53 h55 r90
  text "measurement" at 124,1587.6 h80
  text "RESET" at 1359,1566.98 h55 r90
  text "GND / DETECT" at 1506,1559.6 h55 r90
  text "P0.24" at 2274.31,1380.77 h60
  text "5V" at 2726.31,1378.77 h60
  text "P0.23" at 2726.31,1281.77 h60
  text "P0.25" at 2272.31,1280.77 h60
  text "DETECT" at 2722.84,1183.6 h60
  text "RESET" at 2242.31,1180.77 h60
  text "NORDIC" at 3843,931.6 h150 r90
  text "SEMICONDUCTOR" at 3901.69,928.21 h65 r90
  text "Button 1" at 2920.89,877.45 h90
  text "Button 2" at 3352.89,877.45 h90
  text "External supply" at 91,814.6 h80
  text "www.nordicsemi.com" at 3980.92,735.93 h83 r90
  text "-" at 542,718.6 h70
  text "GND" at 1824,629.6 h70
  text "Debug in" at 2291,630 h80
  text "+" at 542,618.6 h70
  text "IF BOOT/RESET" at 601,442.6 h80
  text "Button 4" at 3354.89,436.89 h90
  text "Button 3" at 2917.89,436.45 h90
  text "N.C." at 1821,411.6 h70 r90
  text "VDD" at 1116.75,411.47 h70 r90
  text "VDD" at 1216.75,411.47 h70 r90
  text "RESET" at 1316.75,411.47 h70 r90
  text "VDD" at 1416.75,411.47 h70 r90
  text "5V" at 1516.75,411.47 h70 r90
  text "GND" at 1616.75,411.47 h70 r90
  text "GND" at 1716.75,411.47 h70 r90
  text "P0.03 (A0)" at 2016.75,411.47 h70 r90
  text "P0.04" at 2116.75,411.47 h70 r90
  text "P0.28" at 2216.75,411.47 h70 r90
  text "P0.29" at 2316.75,411.47 h70 r90
  text "P0.30" at 2416.75,411.47 h70 r90
  text "P0.31" at 2516.75,411.47 h70 r90
  text "NFC" at 2680.46,187.54 h90
  text "OFF" at 115,73.6 h70
  text "ON" at 250,73.6 h70
  text "GND" at 780,29.6 h70
  text "Power" at 132,19.6 h80
Bottom Overlay:
  drawing of 11657 lines, arcs and shapes, not listed
  text "J-Link" at 363.88,2400.2 h57 r90
  text "www.segger.com" at 409.18,2397 h66 r90
  text "TM" at 347.28,2263.6 h37 r90
  text "Pb" at 3807.28,2257.6 h120 r90
  text "S" at 290.67,2255.2 h53 r90
  text "E" at 290.67,2220.17 h53 r90
  text "Technology" at 363.88,2213.1 h57 r90
  text "G" at 290.67,2189.3 h53 r90
  text "G" at 290.67,2150.3 h53 r90
  text "E" at 290.67,2110 h53 r90
  text "P0.27 (SCL)" at 760,2090.6 h65 r90
  text "P0.26 (SDA)" at 860,2090.6 h65 r90
  text "P0.02 (AREF)" at 960,2090.6 h65 r90
  text "GND" at 1060,2090.6 h65 r90
  text "P0.25 (D13)" at 1160,2090.6 h65 r90
  text "P0.24 (D12)" at 1260,2090.6 h65 r90
  text "P0.23 (D11)" at 1360,2090.6 h65 r90
  text "P0.22 (D10)" at 1460,2090.6 h65 r90
  text "P0.20 (D9)" at 1560,2090.6 h65 r90
  text "P0.19 (D8)" at 1660,2090.6 h65 r90
  text "P0.18 (D7)" at 1820,2090.6 h65 r90
  text "P0.17 (D6)" at 1920,2090.6 h65 r90
  text "P0.16 (D5)" at 2020,2090.6 h65 r90
  text "P0.15 (D4)" at 2120,2090.6 h65 r90
  text "P0.14 (D3)" at 2220,2090.6 h65 r90
  text "P0.13 (D2)" at 2320,2090.6 h65 r90
  text "P0.12 (D1)" at 2420,2090.6 h65 r90
  text "P0.11 (ARDUINO D0)" at 2520,2090.6 h65 r90
  text "P0.10" at 2720,2090.6 h70 r90
  text "P0.09" at 2820,2090.6 h70 r90
  text "P0.08" at 2920,2090.6 h70 r90
  text "P0.07" at 3020,2090.6 h70 r90
  text "P0.06" at 3120,2090.6 h70 r90
  text "P0.05" at 3220,2090.6 h70 r90
  text "P0.21" at 3320,2090.6 h70 r90
  text "P0.00" at 3521,2089.6 h70 r90
  text "P0.01" at 3419,2089.28 h70 r90
  text "R" at 290.67,2077.1 h53 r90
  text "GPIO" at 1112,1791.95 h78.5 r90
  text "GPIO" at 2839,1791.95 h78.5 r90
  text "P0.00" at 1263,1787.09 h75 r90
  text "P0.01" at 1475,1787.09 h75 r90
  text "P0.05" at 1634,1787.09 h75 r90
  text "P0.06" at 1740,1787.09 h75 r90
  text "P0.07" at 1846,1787.09 h75 r90
  text "P0.08" at 1952,1787.09 h75 r90
  text "P0.09" at 2092,1787.09 h75 r90
  text "P0.10" at 2272,1787.09 h75 r90
  text "P0.13" at 2937,1787.09 h75 r90
  text "P0.14" at 3043,1787.09 h75 r90
  text "P0.15" at 3149,1787.09 h75 r90
  text "P0.16" at 3255,1787.09 h75 r90
  text "P0.17" at 3361,1787.09 h75 r90
  text "P0.18" at 3467,1787.09 h75 r90
  text "P0.19" at 3573,1787.09 h75 r90
  text "P0.20" at 3679,1787.09 h75 r90
  text "P0.21" at 3785,1785.09 h75 r90
  text "Function" at 1112,1576.6 h78.5 r90
  text "Function" at 2839,1576.6 h78.5 r90
  text "Button 1" at 2937,1564.09 h75 r90
  text "Button 2" at 3043,1564.09 h75 r90
  text "Button 3" at 3149,1564.09 h75 r90
  text "Button 4" at 3255,1564.09 h75 r90
  text "RESET" at 3784,1539.09 h75 r90
  text "LED 1" at 3361,1519.09 h75 r90
  text "LED 2" at 3467,1519.09 h75 r90
  text "LED 3" at 3573,1519.09 h75 r90
  text "LED 4" at 3679,1519.09 h75 r90
  text "NFC1" at 2093,1518.09 h75 r90
  text "NFC2" at 2273,1517.09 h75 r90
  text "XL1" at 1263,1504.09 h75 r90
  text "XL2" at 1475,1504.09 h75 r90
  text "RTS" at 1634,1504.09 h75 r90
  text "TXD" at 1740,1504.09 h75 r90
  text "CTS" at 1846,1504.09 h75 r90
  text "RXD" at 1952,1504.09 h75 r90
  text "SB13/22" at 1634,1261.09 h75 r90
  text "SB14/23" at 1740,1261.09 h75 r90
  text "SB15/24" at 1846,1261.09 h75 r90
  text "SB16/25" at 1952,1261.09 h75 r90
  text "SB17" at 3785,1257.09 h75 r90
  text "SB2" at 1210,1241.09 h75 r90
  text "SB4" at 1316,1241.09 h75 r90
  text "SB1" at 1422,1241.09 h75 r90
  text "SB3" at 1528,1241.09 h75 r90
  text "SB5" at 3361,1241.09 h75 r90
  text "SB6" at 3467,1241.09 h75 r90
  text "SB7" at 3573,1241.09 h75 r90
  text "SB8" at 3679,1241.09 h75 r90
  text "Short" at 1112,1219.28 h78.5 r90
  text "Short" at 2839,1219.28 h78.5 r90
  text "GPIO" at 3766,977.09 h70 r90
  text "GPIO" at 2316.73,974.69 h70 r90
  text "GPIO" at 1433.72,974.09 h70 r90
  text "GPIO" at 1927.72,974.09 h70 r90
  text "*" at 3017.45,974.09 h100 r90
  text "*" at 3635.45,974.09 h100 r90
  text "IF MCU" at 1641,950.59 h70 r90
  text "PIN" at 2039.28,887.69 h70 r90
  text "HW" at 1112,879.28 h78.5 r90
  text "HW" at 2839,879.28 h78.5 r90
  text "SB1x" at 1836,850.09 h50 r90
  text "SB2x" at 1770,841.09 h50 r90
  text "VDD" at 3395,785.09 h70 r90
  text "NFC" at 2160.28,771.69 h70 r90
  text "PIN" at 1256.22,755.09 h70 r90
  text "PIN" at 1927.72,755.09 h70 r90
  text "PIN" at 3766.22,755.01 h70 r90
  text "mbed.org" at 590,671 h70 r90
  text "I/O EXPANDER" at 2839,639.28 h78.5 r90
  text "(" at 2978,636.09 h120 r90
  text "PIN" at 3374,636.34 h70 r90
  text "P0.03 (A0)" at 2015,630 h65 r90
  text "P0.04 (A1)" at 2115,629.6 h65 r90
  text "P0.28 (A2)" at 2215,629.6 h65 r90
  text "P0.29 (A3)" at 2315,629.6 h65 r90
  text "P0.31 (A5)" at 2515,630.28 h65 r90
  text "P0.30 (A4)" at 2414.75,628.92 h65 r90
  text "RESET" at 1319.75,561.47 h65 r90
  text ")" at 2978,516.09 h120 r90
  text "GND" at 1716.75,515.45 h65 r90
  text "GND" at 1619.75,509.45 h65 r90
  text "N.C." at 1821.75,509.45 h70 r90
  text "VDD" at 1120,506.28 h65 r90
  text "VDD" at 1220,506.28 h65 r90
  text "VDD" at 1420,506.28 h65 r90
  text "nRF" at 3583,496.09 h80 r90
  text "5V" at 1521,465.28 h65 r90
  text "*" at 2958,459.09 h100 r90
  text "EXP" at 3328,436.09 h60 r90
  text "(" at 2978,396.09 h120 r90
  text "I2C" at 3438,366.09 h70 r90
  text "DETECT" at 3178,336.09 h70 r90
  text ")" at 2978,236.09 h120 r90
Mechanical 1:
  the board outline again, w10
